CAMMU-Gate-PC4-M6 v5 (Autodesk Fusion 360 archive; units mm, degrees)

design "CAMMU-Gate-PC4-M6" references "MR63ZZ", "Slider T-Nut for 2020 - M5"
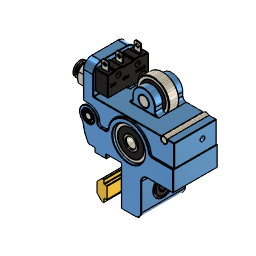
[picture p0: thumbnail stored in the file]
description: Part Number
part number: CAMMU-Linear-Rail-Lead-Screw
part number: Endstop Limit Switch v1
part number: Screw
part number: Brass body
part number: Brass NUT
part number: 625Z_1
description: STEP AP214
part number: PC4-M6
named bodies: "Gate bottom (NEW)", "Gate top (NEW)-PC4-M6", "3x3x22 pin", "5x5x15 shaft", "3x3x21.5 pin", "Slider-Nut-Spacer-12mm", "Magnet 3x3x10", "Magnet 3x3x10 (1)"

design "MR63ZZ"
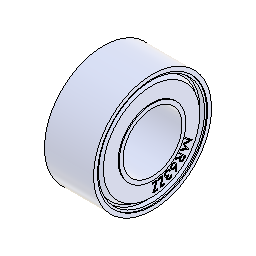
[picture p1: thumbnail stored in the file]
description: STEP AP214
part number: MR63ZZ
description: Part Number
part number: outer shell - mz63zz
part number: inner shell - mz63zz
part number: 1mm ball bearing sphere
part number: MR63ZZ - seal
base_feature "Base Feature1"
base_feature "Base Feature1"
base_feature "Base Feature1"
base_feature "Base Feature1"
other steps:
create_component "CreateComponent1"
create_component "CreateComponent2"
create_component "CreateComponent3"
create_component "CreateComponent4"

design "Slider T-Nut for 2020 - M5"
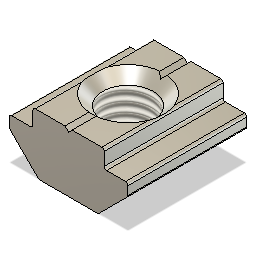
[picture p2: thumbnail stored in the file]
sketch "Sketch1"
  dimension "d1" = 10
  dimension "d4" = 5
  dimension "d5" = 45
  dimension "d6" = 1
  dimension "d7" = 5
  dimension "d8" = 6
  dimension "d9" = 2
  dimension "d10" = 2
  dimension "d12" = 45
  dimension "d13" = 0.3
  dimension "d14" = 5
  dimension "d15" = 1.5
  dimension "d16" = 0.2
extrude "Extrude1" new body sketch "Sketch1" blind 10
hole "Hole1" HoleDepth 5.834 HoleDiameter 4.234 TipAngle 180 CSDiameter 6 CSAngle 90 RefDim1 5 RefDim2 5
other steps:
thread "Thread1"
